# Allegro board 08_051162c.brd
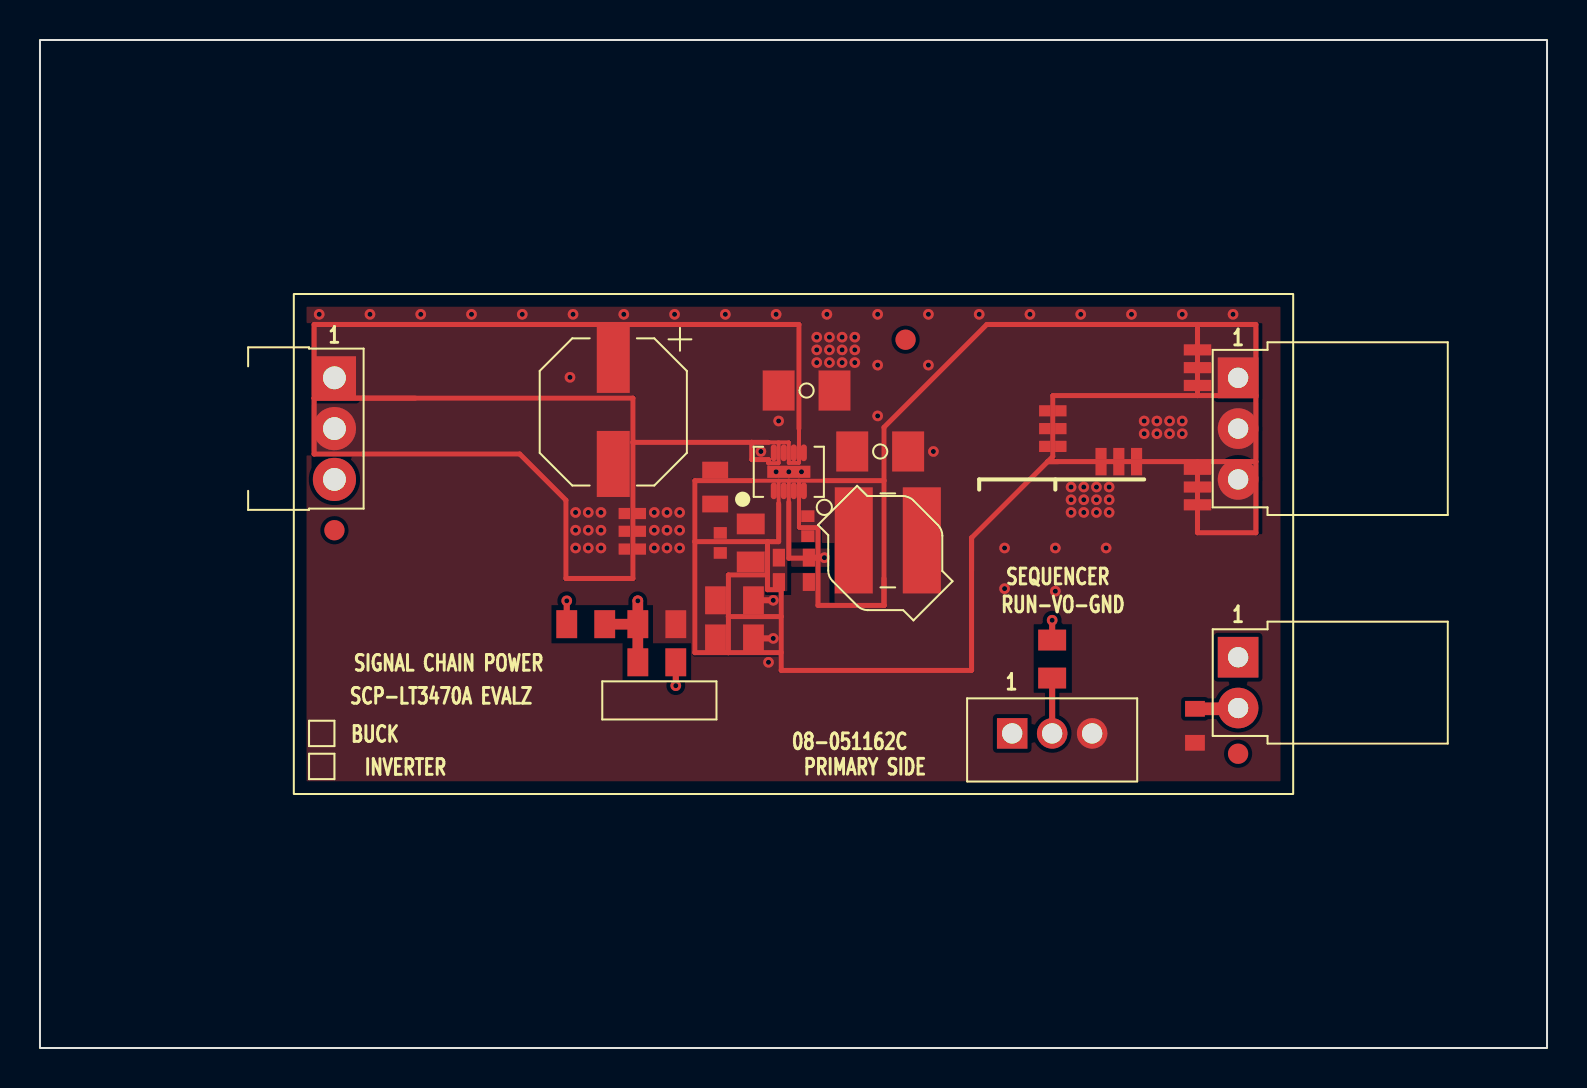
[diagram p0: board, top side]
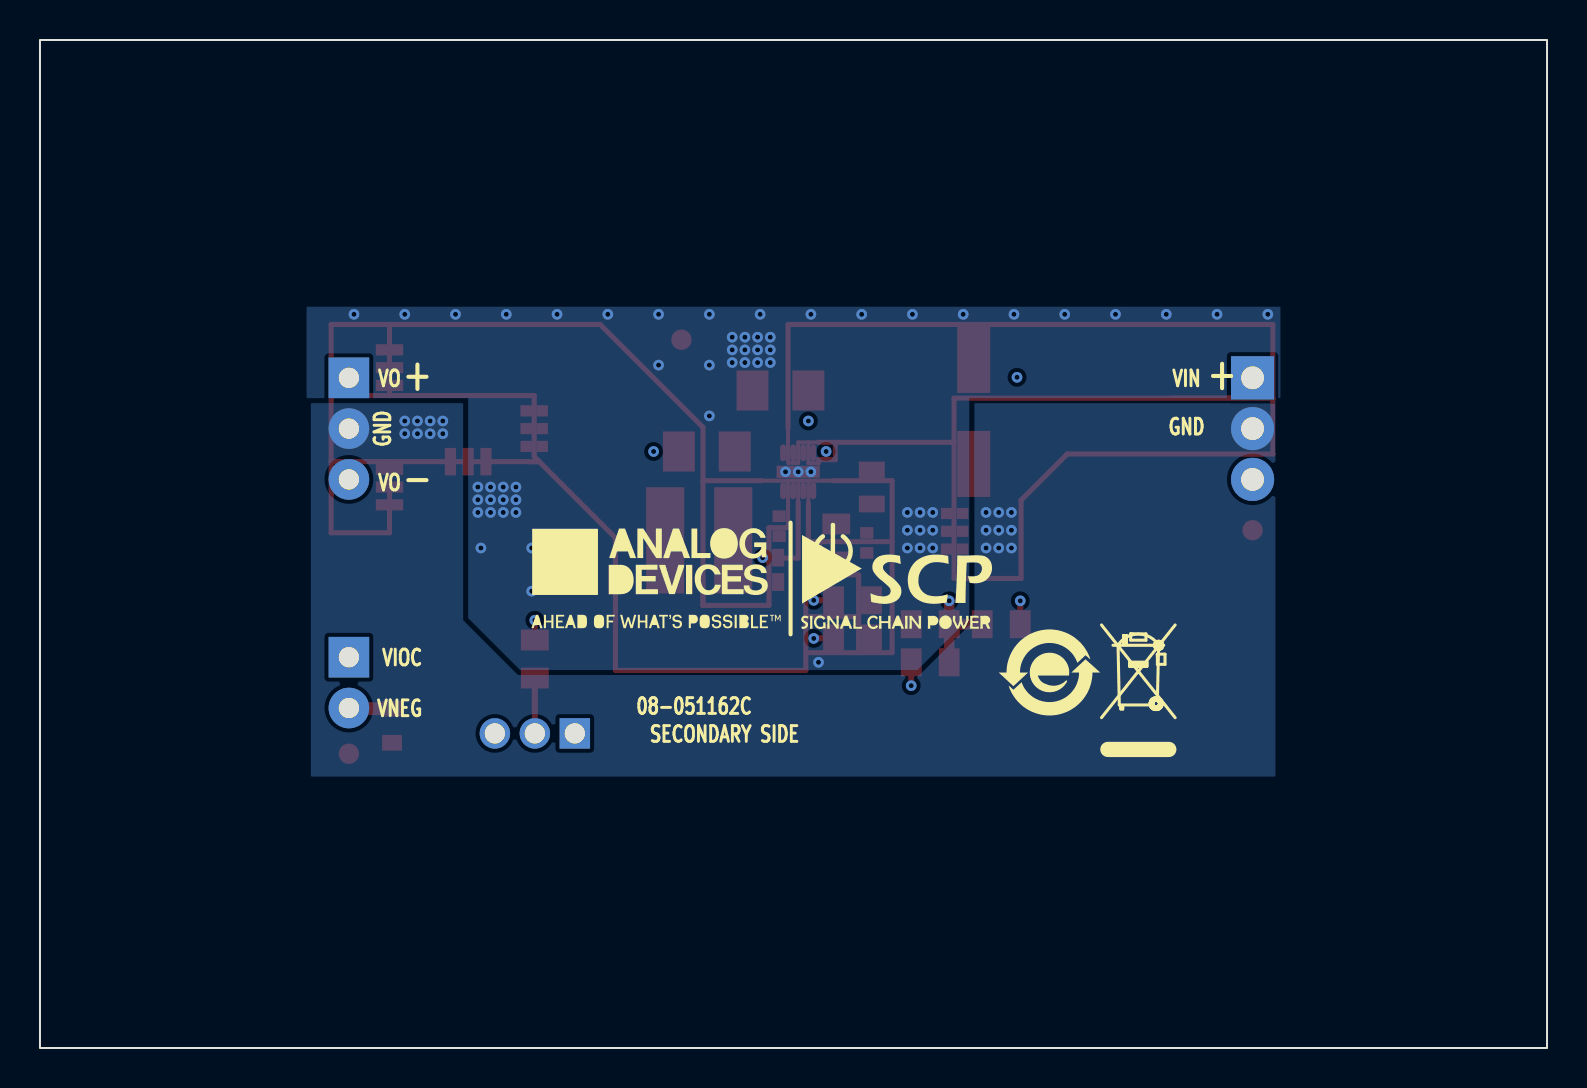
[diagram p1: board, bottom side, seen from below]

Outline 75.4 x 50.4 mm; copper layers: TOP, L2, L3, BOTTOM. Coordinates in mm from the lower left corner of the outline.
Outline path: rectangle 0,0 75.4,50.4

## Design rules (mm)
constraint set DEFAULT: min track width 0.203

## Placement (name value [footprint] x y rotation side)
C1  10UF  [CPLSMSQ260H240]  28.68 31.8 90 top
C2  1.0UF  [C1206H71]  38.35 32.87 0 top
C3  0.22UF  [C0402]  38.42 26.09 90 top
C4  22UF  [C1206H71]  42.04 29.83 180 top
C6  22pF  [C0402]  34.04 25.25 90 top
INPUT  PBC03SBAN  [CNTHMHDRRA1X3L300W100H145]  14.73 33.51 270 top
L1  33UH  [LSMSQ185H118]  42.42 25.38 270 top
NOREF  -  []  62.7 12.7 90 top
NOREF#2  -  []  62.72 37.77 180 top
NOREF#3  -  []  87.12 137.01 0 top
NOREF#4  -  []  -103.06 183.47 0 top
NOREF#5  -  [unnamed#2]  43.31 35.41 0 top
NOREF#6  -  []  12.7 12.7 0 top
NOREF#7  -  []  -184.02 -185.57 0 top
NOREF#8  -  []  38.21 58.73 0 top
NOREF#9  -  [unnamed#2]  59.94 14.71 0 top
NOREF#10  -  []  12.68 12.63 0 top
NOREF#11  -  []  62.72 12.63 90 top
NOREF#12  -  []  -223.77 -184.68 0 top
NOREF#13  -  []  -111.79 -29.36 0 top
NOREF#14  -  [unnamed#2]  14.73 25.89 0 top
NOREF#15  -  []  -336.95 -273.25 0 top
NOREF#16  -  []  12.68 37.77 270 top
NOREF#17  -  []  32.51 23.6 180 bottom
NOREF#18  -  []  24.89 18.77 180 bottom
NOREF#19  -  []  20.65 14.61 180 bottom
NOREF#20  -  []  44.87 23.45 180 bottom
OUTPUT  PPPC031LGBN-RC  [CNHDRRA1X3H108]  59.94 33.51 270 top
P1  53253-0370  [CNTHMHDR1X3L315W144H224]  48.64 15.73 0 top
R1  100K  [R0805]  27.3 21.19 180 top
R2  324K  [R0805]  35.56 25.25 270 top
R3  200K  [R0805#2]  33.78 28.05 90 top
R4  -  [NC0402L]  29.64 26.72 0 top
R5  -  [NC0402L]  29.64 25.84 0 top
R6  -  [NC0402L]  29.64 24.95 0 top
R7  0  [R0805]  30.86 21.19 0 top
R8  0  [R0805]  34.75 22.38 180 top
R9  0  [R0805]  34.75 20.48 180 top
R10  -  [NC0402L]  54.86 29.32 90 top
R11  -  [NC0402L]  53.98 29.32 90 top
R12  -  [NC0402L]  53.09 29.32 90 top
R13  -  [NC0402L]  50.67 31.86 180 top
R14  -  [NC0402L]  50.67 30.97 180 top
R15  -  [NC0402L]  50.67 30.08 180 top
R16  -  [NC0402L]  57.91 28.94 0 top
R17  -  [NC0402L]  57.91 28.05 0 top
R18  -  [NC0402L]  57.91 27.16 0 top
R19  -  [NC0402L]  57.91 34.91 0 top
R20  -  [NC0402L]  57.91 34.02 0 top
R21  -  [NC0402L]  57.91 33.13 0 top
R22  0  [R0805]  50.64 19.45 90 top
R23  0  [R0805]  30.86 19.29 180 top
R24  0  [R0603]  57.78 16.11 90 top
R25  0  [R0603]  37.72 24.52 180 top
R26  0  [R0603]  37.72 23.3 0 top
U1  LT3470AEDDB#PBF  [DFN8_3X2_PAD2_15X0_56]  37.47 28.81 0 top
VIOC  PPPC021LGBN-RC  [CNTHFHDRRA1X2L220W335H108]  59.94 19.54 270 top

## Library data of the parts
C1 = CAPP: Tolerance: 20; User Part Number: UPN; alternate symbols: (); part number: CAPP_SM-10UF,50V,20,E033764,CPLSMSQ260H240; tolerance: 20
C2 = CAP: Tolerance: 10; User Part Number: UPN; alternate symbols: (); part number: CAP_SM-1.0UF,50V,10,E031061,C1206H71; tolerance: 10
C3 = CAP: User Part Number: UPN; Tolerance: 10; alternate symbols: (); part number: CAP_SM-0.22UF,50V,10,E038241,C0402; tolerance: 10
C4 = CAP: Tolerance: 10; User Part Number: UPN; alternate symbols: (); part number: CAP_SM-22UF,25V,10,E033991,C1206H71; tolerance: 10
C6 = CAP: User Part Number: UPN; Tolerance: 5; alternate symbols: (); part number: CAP_SM-22PF,50V,5,E021945,C0402; tolerance: 5
INPUT = CN3P: Tolerance: N/A; User Part Number: UPN; alternate symbols: (CNTHMHDRRA1X3L300W100H145_SCP); part number: CN3P_TH-PBC03SBAN,E034137,CNTHMHDRRA1X3L300W100H145; tolerance: N/A
L1 = IND: Tolerance: 20; User Part Number: UPN; alternate symbols: (); part number: IND_SM-33UH,20,E038510,LSMSQ185H118; tolerance: 20
OUTPUT = CN3P: User Part Number: UPN; Tolerance: N/A; alternate symbols: (CNHDRRA1X3H108_SCP); part number: CN3P_TH-PPPC031LGBN-RC,E034111,CNHDRRA1X3H108; tolerance: N/A
P1 = CN3P: Tolerance: N/A; User Part Number: UPN; alternate symbols: (); part number: CN3P_TH-53253-0370,E033940,CNTHMHDR1X3L315W144H224; tolerance: N/A
R1 = RES: User Part Number: UPN; Tolerance: 1; alternate symbols: (R0805L); part number: RES_SM-100K,E003488,1/8W,1,R0805; tolerance: 1
R2 = RES: User Part Number: UPN; Tolerance: 1; alternate symbols: (); part number: RES_SM-324K,E033732,1/8W,1,R0805; tolerance: 1
R3 = RES: User Part Number: UPN; Tolerance: 1; alternate symbols: (R0805L); part number: RES_SM-200K,E003524,1/8W,1,R0805; tolerance: 1
R4-R6 R10-R21 = NC2P: User Part Number: UPN; Tolerance: N/A; alternate symbols: (); part number: NC2P_SM-NC0402L,E033984,NC0402L; tolerance: N/A
R7-R9 R22 R23 = RES: User Part Number: UPN; Tolerance: N/A; alternate symbols: (R0805L); part number: RES_SM-0,E030875,1/8W,N/A,R0805; tolerance: N/A
R24-R26 = RES: User Part Number: UPN; Tolerance: 5; alternate symbols: (R0603L); part number: RES_SM-0,E006826,1/10W,5,R0603; tolerance: 5
U1 = ICLT3470A: User Part Number: UPN; Tolerance: N/A; alternate symbols: (); part number: ICLT3470A_SM-LT3470AEDDB#PBF,E033524,DFN8_3X2_PAD2_15X0_56; tolerance: N/A
VIOC = CN2P: Tolerance: N/A; User Part Number: UPN; alternate symbols: (CNTHFHDRRA1X2L220W335H108_SCP); part number: CN2P_TH-PPPC021LGBN-RC,E034113,CNTHFHDRRA1X2L220W335H108; tolerance: N/A

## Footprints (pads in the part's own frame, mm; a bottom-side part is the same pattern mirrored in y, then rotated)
C0402
  rect 0.584x0.66 smd: 1(-0.5,0) 2(0.5,0)
C1206H71
  rect 1.6x2.007 smd: 1(-1.397,0) 2(1.397,0)
CNHDRRA1X3H108
  rect 2.032x2.032 hole 1.016: 1(0,0)
  round 2.032 hole 1.016: 2(2.54,0) 3(5.08,0)
CNTHFHDRRA1X2L220W335H108
  rect 2.032x2.032 hole 1.016: 1(0,0)
  round 2.032 hole 1.016: 2(2.54,0)
CNTHMHDR1X3L315W144H224
  rect 1.524x1.524 hole 1.016: 1(0,0)
  round 1.524 hole 1.016: 2(2,0) 3(4,0)
CNTHMHDRRA1X3L300W100H145
  rect 2.159x2.159 hole 1.143: 1(0,0)
  round 2.159 hole 1.143: 2(2.54,0) 3(5.08,0)
CPLSMSQ260H240
  rect 3.302x1.651 smd: N(-2.601,0) P(2.601,0)
DFN8_3X2_PAD2_15X0_56
  oval 0.305x0.838 smd: 1(-0.75,-0.95) 2(-0.25,-0.95) 3(0.25,-0.95) 4(0.75,-0.95) 5(0.75,0.95) 6(0.25,0.95) 7(-0.25,0.95) 8(-0.75,0.95)
  rect 2.159x0.61 smd: PAD(0,0)
LSMSQ185H118
  rect 5.309x1.905 smd: 1(0,-1.703) 2(0,1.703)
NC0402L
  rect 0.572x0.559 smd: 1(-0.4,0) 2(0.4,0)
R0603
  rect 0.787x0.991 smd: 1(-0.85,0) 2(0.85,0)
R0805
  rect 1.041x1.397 smd: 1(-0.95,0) 2(0.95,0)
R0805#2
  rect 0.838x1.295 smd: 1(-0.85,0) 2(0.85,0)
unnamed#2
  round 1.016 smd: (0,0)

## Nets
GND: C1.N(N2) INPUT.2 OUTPUT.2 R4.1 R5.1 R6.1 R10.2(N2) R11.2(N2) R12.2(N2) R13.1 R14.1 R15.1
VIN: C1.P C2.1 INPUT.1 R1.2(N2) R25.1 U1.6(VIN)
RUN: P1.1 R23.1
UNNAMED_2_CAP_I13_N1: C6.1 R2.2(N2) R8.2(N2) R9.2(N2)
UNNAMED_2_CAP_I13_N2: C6.2(N2) R2.1 R3.1 U1.1
UNNAMED_2_CAP_I14_N1: C3.1 U1.3
UNNAMED_2_CAP_I14_N2: C3.2(N2) L1.1 U1.4
UNNAMED_2_CAP_I24_N1: C4.1 L1.2(N2) R8.1 R13.2(N2) R14.2(N2) R15.2(N2) R19.1 R20.1 R21.1 R26.2(N2)
UNNAMED_2_CN2P_I35_N2: R24.2(N2) VIOC.2(N2)
UNNAMED_2_CN3P_I1_N2: P1.2 R22.1
UNNAMED_2_ICLT3470A_I37_BIAS: R25.2(N2) R26.1 U1.2
UNNAMED_2_ICLT3470A_I37_SHDNN: R1.1 R7.1 R23.2(N2) U1.8
VIOC: R9.1 VIOC.1
VNEG: C2.2(N2) C4.2(N2) P1.3(N3) R3.2(N2) R4.2(N2) R5.2(N2) R6.2(N2) R7.2(N2) R10.1 R11.1 R12.1 R16.1 R17.1 R18.1 R24.1 U1.5 U1.7 U1.PAD
VO+: OUTPUT.1 R19.2(N2) R20.2(N2) R21.2(N2) R22.2(N2)
VO-: OUTPUT.3(N3) R16.2(N2) R17.2(N2) R18.2(N2)

Pads without a net: INPUT 3

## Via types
v1: diameter 0.533, hole 0.254, TOP to BOTTOM, 92 vias

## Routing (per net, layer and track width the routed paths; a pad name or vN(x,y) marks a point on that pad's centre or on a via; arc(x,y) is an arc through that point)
GND:
  vias: v1(26.8,26.78) v1(26.8,25.89) v1(26.8,25) v1(27.43,26.78) v1(27.43,25.89) v1(27.43,25) v1(28.07,26.78) v1(28.07,25.89) v1(28.07,25) v1(55.24,31.35) v1(55.24,30.72) v1(55.88,31.35) v1(55.88,30.72) v1(56.52,31.35) v1(56.52,30.72) v1(57.15,31.35) v1(57.15,30.72)
VIN: length 21.8
  TOP w0.305: R25.1 v1(39.24,24.52) ; R1.2 v1(26.36,22.36)
  L3 w0.305: v1(39.24,24.52) 39.24,29.06 v1(36.96,31.35) ; v1(26.36,22.36) 25.4,23.31 25.4,32.42 v1(26.52,33.53)
RUN: length 19
  TOP w0.305: R23.1 v1(31.81,18.12)
  L3 w0.305: v1(31.81,18.12) 34.2,15.73 P1.1
UNNAMED_2_CAP_I24_N1: length 13.1
  TOP w0.305: v1(36.69,22.38) 36.69,22.38 R8.1
  L3 w0.305: v1(36.69,22.38) 37.31,22.38 37.31,22.38 39.04,22.38 44.7,28.04 v1(44.7,29.83)
UNNAMED_2_CN2P_I35_N2: length 2.2
  TOP w0.635: R24.2 59.9,16.96 VIOC.2
UNNAMED_2_CN3P_I1_N2: length 2.8
  TOP w0.305: R22.1 P1.2
UNNAMED_2_ICLT3470A_I37_SHDNN: length 15.3
  TOP w0.533: R7.1 R1.1 ; R7.1 R23.2 ; R7.1 v1(29.91,22.36)
  L3 w0.305: v1(29.91,22.36) 30.89,22.36 36.07,27.54 v1(36.07,29.83)
VIOC: length 25.9
  TOP w0.305: R9.1 v1(36.69,20.48)
  L3 w0.305: VIOC.1 58.42,18.02 39.28,18.02 v1(36.69,20.48)
VNEG: length 0
  vias: v1(13.97,36.68) v1(16.51,36.68) v1(19.05,36.68) v1(21.59,36.68) v1(24.13,36.68) v1(26.67,36.68) v1(29.21,36.68) v1(30.73,26.78) v1(30.73,25.89) v1(30.73,25) v1(31.37,26.78) v1(31.37,25.89) v1(31.37,25) v1(31.75,36.68) v1(32,26.78) v1(32,25.89) v1(32,25) v1(34.29,36.68) v1(36.45,19.29) v1(36.83,36.68) v1(36.83,28.81) v1(37.47,28.81) v1(38.1,28.81) v1(38.86,35.54) v1(38.86,34.91) v1(38.86,34.27) v1(39.37,36.68) v1(39.5,35.54) v1(39.5,34.91) v1(39.5,34.27) v1(40.13,35.54) v1(40.13,34.91) v1(40.13,34.27) v1(40.77,35.54) v1(40.77,34.91) v1(40.77,34.27) v1(41.91,36.68) v1(41.91,34.14) v1(41.91,31.6) v1(44.45,36.68) v1(44.45,34.14) v1(46.99,36.68) v1(48.26,25) v1(48.26,22.97) v1(49.53,36.68) v1(50.8,25) v1(50.8,22.84) v1(51.59,28.05) v1(51.59,27.41) v1(51.59,26.78) v1(52.07,36.68) v1(52.22,28.05) v1(52.22,27.41) v1(52.22,26.78) v1(52.86,28.05) v1(52.86,27.41) v1(52.86,26.78) v1(53.34,25) v1(53.49,28.05) v1(53.49,27.41) v1(53.49,26.78) v1(54.61,36.68) v1(57.15,36.68) v1(59.69,36.68)
VO+: length 17
  TOP w0.305: R22.2 v1(50.64,21.39)
  L3 w0.305: v1(50.64,21.39) 58.17,28.91 58.17,31.73 OUTPUT.1

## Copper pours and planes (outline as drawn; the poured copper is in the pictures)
GND on TOP: 50.73,29.45 50.8,29.52 50.8,32.49 60.96,32.49 60.96,29.45
GND on TOP: 26.44,23.6 26.44,27.44 24.06,29.83 13.59,29.83 13.59,32.37 29.54,32.37 29.54,23.6
GND on BOTTOM: 54.23,32.24 61.85,32.24 61.85,13.57 13.59,13.57 13.59,32.24 28.65,32.24 28.65,21.39 31.39,18.65 51.49,18.65 54.23,21.39
GND on L2: 54.23,32.49 61.85,32.49 61.85,13.57 13.59,13.57 13.59,32.37 28.65,32.37 28.65,21.39 31.39,18.65 51.49,18.65 54.23,21.39
VIN on TOP: 37.57,24.97 37.57,24.06 39.5,24.06 39.5,24.97
VIN on TOP: 37.57,29.36 37.57,30.39 36.53,30.39 36.5,30.41 29.79,30.41 29.79,32.62 13.59,32.62 13.59,36.05 37.85,36.05 37.85,30.92 37.87,30.89 37.87,29.36
UNNAMED_2_CAP_I13_N1 on TOP: 32.89,19.77 32.89,25.19 36.27,25.19 36.27,23.78 34.32,23.78 34.32,19.77
UNNAMED_2_CAP_I13_N2 on TOP: 32.89,25.44 32.89,28.24 35.74,28.24 35.76,28.26 36.86,28.26 36.86,27.3 36.83,27.28 36.83,25.44
UNNAMED_2_CAP_I14_N1 on TOP: 37.57,25.28 37.57,28.26 37.87,28.26 37.87,25.89 38.84,25.89 38.84,25.28
UNNAMED_2_CAP_I14_N2 on TOP: 38.07,28.26 39.23,28.26 39.25,28.24 42.1,28.24 42.1,22.26 39.75,22.26 39.75,25.25 39.12,25.25 39.12,26.14 38.07,26.14
UNNAMED_2_CAP_I24_N1 on TOP: 34.57,21.7 34.57,23.53 36.27,23.53 36.27,22.66 36.96,22.66 36.96,21.7
UNNAMED_2_CAP_I24_N1 on TOP: 37.21,19.01 37.21,23.76 39.5,23.76 39.5,22 42.35,22 42.35,22.06 42.37,22.08 42.37,22.18 42.35,22.2 42.35,30.98 47.42,36.05 57.78,36.05 57.78,32.75 50.55,32.75 50.55,29.62 46.48,25.56 46.48,19.01
UNNAMED_2_ICLT3470A_I37_BIAS on TOP: 37.06,28.28 37.06,25.2 36.53,25.2 36.53,22.84 37.39,22.84 37.39,28.28
VIOC on TOP: 34.57,19.77 34.57,21.44 36.96,21.44 36.96,19.77
VNEG on TOP: 13.34,13.34 13.34,37.06 62.06,37.06 62.06,13.34 ; 4 cut-outs
VNEG on BOTTOM: 13.34,37.06 62.06,37.06 62.06,32.49 53.98,32.49 53.98,21.5 51.38,18.9 31.5,18.9 28.91,21.5 28.91,32.49 13.34,32.49
VNEG on L2: 13.34,37.06 62.06,37.06 62.06,32.75 53.98,32.75 53.98,21.5 51.38,18.9 31.5,18.9 28.91,21.5 28.91,32.62 13.34,32.62
VNEG on L3: 13.34,13.34 13.34,37.06 62.06,37.06 62.06,13.34
VO+ on TOP: 58.04,32.75 58.04,36.05 60.96,36.05 60.96,32.75
VO- on TOP: 58.04,25.89 58.04,29.19 60.96,29.19 60.96,25.89

Small or netless copper shapes (teardrops, artwork), in the pictures only: 1 on TOP

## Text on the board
Ref Des/Silkscreen Bottom: VIN | GND | SECONDARY SIDE | 08-051162C | VIOC | VNEG | VO | + | -
User.Comments: AND PLACE MARK ON TICK BOX IN THE PRIMARY SIDE | 5.    INSTALL SOLDER BLOB USING THE TABLE BELOW (SEE DETAILS A) | 4.    RoHS COMPLIANCE: ASSEMBLY VENDOR SHOULD ASSURE COMPLIANCE | 05-051162-02-b | 05-051162-01-b | BOM | WITH LEAD-FREE AND RoHS PCB ASSEMBLY STANDARDS (EU RoHS | DIRECTIVE 2002/95/EC). | SCALE FACTOR: 1:4 | DETAIL A | R13, R14, R15, R16, R17, R18 | R4, R5, R6, R10, R11, R12, R19, R20 AND R21 | PARTS | TICK BOX | BUCK | INVERTER
Ref Des/Silkscreen Top: BUCK | INVERTER | SCP-LT3470A EVALZ | SIGNAL CHAIN POWER | 08-051162C | PRIMARY SIDE | SEQUENCER | RUN-VO-GND
PAGE_OUTLINE: B | C | AS PER ECR-086388 | AS PER ECR-090283 | 07MAY19 | 31OCT19 | J VIERNES
DIMENSION: REF | 0.165 | -0.819 | "0" | HOLE TOLERANCE | PLATED: +/- 3 MILS | UNLESS SPECIFIED | SEE FAB NOTE 15 | DIA MAX | -0.080 | 1.889
User.15: MATERIALS; | ENIG (Electroless Nickel/Immersion Gold) | PER IPC-4552 LATEST REVISION | HOMOGENOUS MATERIALS IN THIS BOARD SHALL BE COMPLIANT | THE EU RoHS DIRECTIVE 2002/95/EC | 15.    THRU VIAS TO BE FILLED WITH SOLDERMASK.
User.17: L2 | 08-      -07
User.18: L3 | 08-      -08
User.45: FIGURE | SIZE | 10.0 | 40.0 | 45.0 | PLATED | FINISHED HOLES IN MILS | ALL UNITS ARE IN MILS | QTY | 92 | 8 | 3 | TOLERANCE/NOTES
